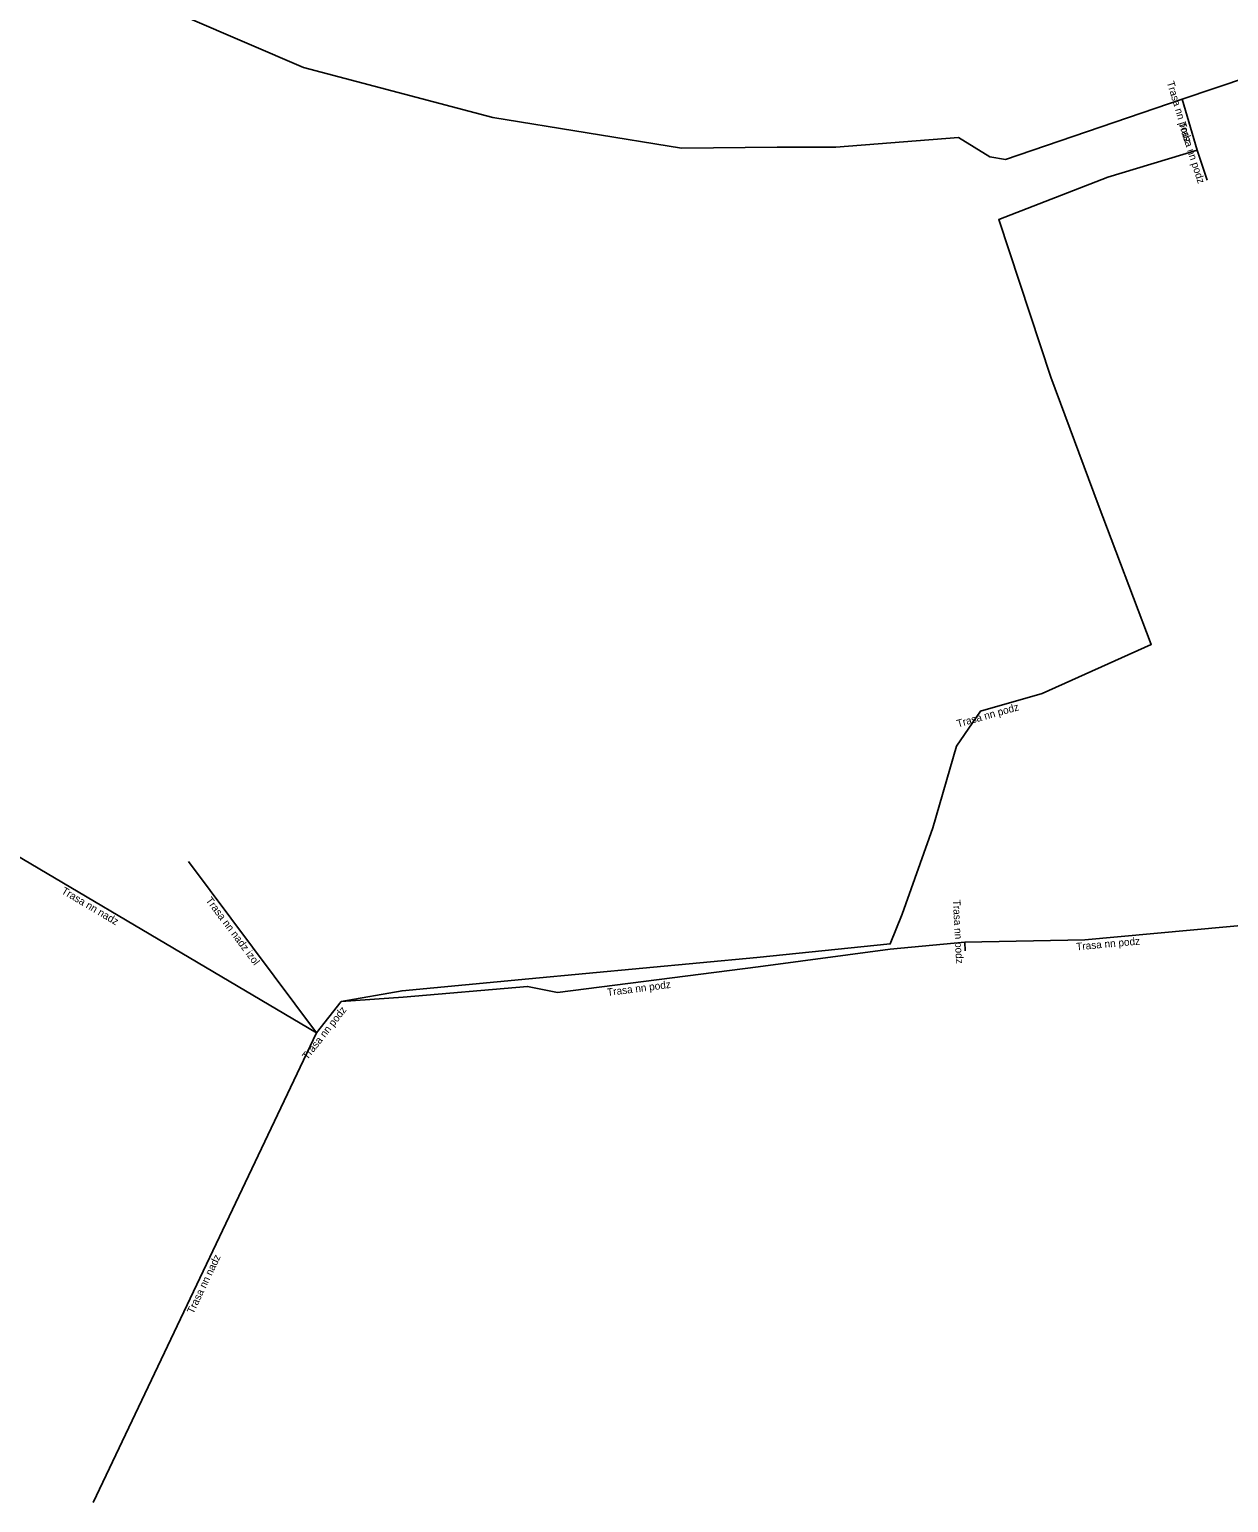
# Model space of a CAD drawing. Extents: x -682605 to -681948, y -1059884 to -1059661.
# Drawn here: x -682524.8 to -682444.9, y -1059883.8 to -1059785.6 of the extents above; entities that cross this region are included whole.
import ezdxf

# ---------------------------------------------------------------- set-up
doc = ezdxf.new("R2010")
doc.units = 0
doc.layers.add('Popiskový text - Ostatní atributy Trasy', color=7, linetype='Continuous')
doc.layers.add('Spojnice NN', color=7, linetype='Continuous')

msp = doc.modelspace()

# ---------------------------------------------------------------- linework, layer by layer
at = {"layer": 'Spojnice NN'}
for points in [[(-682447.96, -1059790.21), (-682459.73, -1059794.22), (-682460.78, -1059794.04), (-682462.86, -1059792.75), (-682471.05, -1059793.41), (-682474.96, -1059793.4), (-682481.35, -1059793.46), (-682493.93, -1059791.42), (-682506.56, -1059788.09), (-682521.987, -1059781.448), (-682525.523, -1059778.638), (-682528.175, -1059775.049), (-682529.632, -1059771.355), (-682532.33, -1059768.34), (-682552.54, -1059758.22), (-682567.03, -1059749.33), (-682579.9, -1059742.47), (-682589.71, -1059735.91), (-682599.88, -1059730.78)], [(-682435.82, -1059799.97), (-682439.5, -1059788.57), (-682441.27, -1059787.95), (-682447.96, -1059790.21)], [(-682447.96, -1059790.21), (-682446.94, -1059793.6)], [(-682446.94, -1059793.6), (-682452.91, -1059795.41), (-682460.18, -1059798.23), (-682456.71, -1059808.73), (-682453.56, -1059817.22), (-682450.01, -1059826.56), (-682457.29, -1059829.84), (-682461.41, -1059831), (-682463.01, -1059833.35), (-682464.59, -1059838.79), (-682466.62, -1059844.55), (-682467.42, -1059846.53), (-682476.33, -1059847.43), (-682491.53, -1059848.85), (-682499.99, -1059849.65), (-682504.05, -1059850.38)], [(-682446.94, -1059793.6), (-682446.29, -1059795.6)], [(-682533.752, -1059835.881), (-682505.69, -1059852.46)], [(-682514.235, -1059841.045), (-682505.69, -1059852.46)], [(-682462.45, -1059846.41), (-682454.44, -1059846.26), (-682442.57, -1059845.16), (-682441.43, -1059845.33)], [(-682504.05, -1059850.38), (-682499.91, -1059850.09), (-682491.62, -1059849.36), (-682489.62, -1059849.78), (-682476.24, -1059848.06), (-682467.43, -1059846.87), (-682462.45, -1059846.41)], [(-682462.45, -1059846.41), (-682462.42, -1059847)], [(-682505.69, -1059852.46), (-682504.05, -1059850.38)], [(-682505.69, -1059852.46), (-682520.603, -1059883.779)]]:
    msp.add_lwpolyline(points, dxfattribs=at)

# ---------------------------------------------------------------- texts
at = {"layer": 'Popiskový text - Ostatní atributy Trasy'}
for s, rotation, p in [('Trasa nn podz', 286.74575, (-682448.979, -1059789.078)), ('Trasa nn podz', 288.00416, (-682448.206, -1059791.808)), ('Trasa nn podz', 15.72475, (-682462.91, -1059832.098)), ('Trasa nn nadz', 329.42545, (-682522.761, -1059843.129)), ('Trasa nn nadz izol', 306.81766, (-682513.114, -1059843.628)), ('Trasa nn podz', 272.91084, (-682463.244, -1059843.594)), ('Trasa nn podz', 5.29451, (-682454.994, -1059846.964)), ('Trasa nn podz', 7.3252, (-682486.279, -1059850.006)), ('Trasa nn podz', 51.74558, (-682506.309, -1059854.295)), ('Trasa nn nadz', 64.53786, (-682513.912, -1059871.24))]:
    msp.add_text(s, height=0.5, rotation=rotation, dxfattribs=at).set_placement(p)

doc.saveas('drawing.dxf')
